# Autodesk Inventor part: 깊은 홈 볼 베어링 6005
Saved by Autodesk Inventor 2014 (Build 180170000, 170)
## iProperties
Created: 2026-04
Part Number: 깊은 홈 볼 베어링 6005
Material: 강철, 연강
Document SubType Name: Modeling
Designer: dg
Density: 7.86 g/cm^3
Appearance: 강철
Author: jhkim
Description: 깊은 그루브 볼 베어링
Creation Date: 2026-03-27
Sending System: Autodesk Inventor 2026
Preprocessor: ST-DEVELOPER v20.1
Author: dg
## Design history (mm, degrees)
node "깊은 홈 볼 베어링 60051"
body "Solid1"
node "Solid1_1"
node "Solid1_2"
node "Solid1_3"
node "Solid1_4"
node "Solid1_5"
node "Solid1_6"
node "Solid1_7"
node "Solid1_8"
node "Solid1_9"
node "Solid1_10"
node "Solid1_11"
node "기준1"
node "기준2"
node "기준3"
node "기준4"
node "기준5"
node "기준6"
node "기준7"
node "기준8"
node "기준9"
node "기준10"
node "기준11"
node "기준12"
